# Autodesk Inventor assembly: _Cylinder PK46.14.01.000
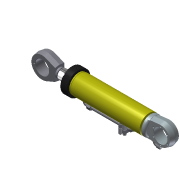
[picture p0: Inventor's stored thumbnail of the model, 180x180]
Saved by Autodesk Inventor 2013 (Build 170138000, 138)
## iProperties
Shininess: 64.0
Length Units: 11269
Angle Units: 11279
Time Units: 11290
Mass Units: 11283
Length Display Precision: 1
Angle Display Precision: 2
Compacted: True
Created: 2004-11
Part Number: _Cylinder PK46.14.01.000
Document SubType Name: Assembly
Designer: ELarisa
Manufacturer: Standard
Standards Organization: Custom
Density: 0.0
Volumn: 0.0
Area: 0.0
PropertySet Name: Model Information
Control State: 0
Master: False
Checked Out: False
Checked Out Date: 2008-10-15
Last Check In Date: 2008-10-15
Author: ELarisa
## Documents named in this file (11)
- C:\Product Design Suite 2013 Test Drive\Model Based Documentation\Workspace\_Cylinder PK46.14.01.000.iam
- C:\Product Design Suite 2013 Test Drive\Model Based Documentation\Workspace\Assemblies\PK46.14.01.010.iam
- C:\Product Design Suite 2013 Test Drive\Model Based Documentation\Workspace\Assemblies\PK46.14.01.020.iam
- C:\Product Design Suite 2013 Test Drive\Model Based Documentation\Workspace\Parts\PK46.14.01.003.ipt
- C:\Product Design Suite 2013 Test Drive\Model Based Documentation\Workspace\Parts\PK46.14.01.004.ipt
- C:\Product Design Suite 2013 Test Drive\Model Based Documentation\Workspace\Parts\PK46.14.01.005.ipt
- C:\Product Design Suite 2013 Test Drive\Model Based Documentation\Workspace\Parts\PK46.14.01.006.ipt
- C:\Product Design Suite 2013 Test Drive\Model Based Documentation\Workspace\Parts\PK46.14.01.015.ipt
- C:\Product Design Suite 2013 Test Drive\Model Based Documentation\Workspace\Parts\PK46.14.01.016.ipt
- C:\Product Design Suite 2013 Test Drive\Model Based Documentation\Workspace\Parts\8.65G.019.ipt
- C:\Product Design Suite 2013 Test Drive\Model Based Documentation\Workspace\Parts\M8-6gx45.58.019(S13).ipt
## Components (12 placed, 10 different names)
1. PK46.14.01.020:1 [sub-assembly] — Insert:80, Mate:7, Mate:9, CylinderStroke, Mate:11, Mate:12, Flush:3
2. PK46.14.01.010:1 [sub-assembly] — Insert:1, Mate:4, Mate:7
3. PK46.14.01.003:1 — Insert:1, CylinderStroke
4. PK46.14.01.004:1 — Insert:80, Insert:81
5. PK46.14.01.005:1 — Insert:81, Insert:82
6. PK46.14.01.006:1 — Insert:82, Mate:11
7. PK46.14.01.015:1 — Flush:1, Mate:5
8. PK46.14.01.016:1 — Flush:2, Mate:5, Insert:88, Insert:89
9. 8.65G.019:25 — Insert:88, Insert:90
10. 8.65G.019:26 — Insert:89, Insert:91
11. M8-6gx45.58.019(S13):1 — Insert:90
12. M8-6gx45.58.019(S13):2 — Insert:91
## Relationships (18: Insert 8, Mate 7, Flush 3)
- Insert:1: PK46.14.01.010:1 ↔ PK46.14.01.003:1
- Insert:80: PK46.14.01.020:1 ↔ PK46.14.01.004:1
- Insert:81: PK46.14.01.004:1 ↔ PK46.14.01.005:1
- Insert:82: PK46.14.01.005:1 ↔ PK46.14.01.006:1
- Flush:1: PK46.14.01.015:1
- Flush:2: PK46.14.01.016:1
- Mate:4: PK46.14.01.010:1
- Mate:5: PK46.14.01.015:1 ↔ PK46.14.01.016:1
- Insert:88: PK46.14.01.016:1 ↔ 8.65G.019:25
- Insert:89: PK46.14.01.016:1 ↔ 8.65G.019:26
- Insert:90: 8.65G.019:25 ↔ M8-6gx45.58.019(S13):1
- Insert:91: 8.65G.019:26 ↔ M8-6gx45.58.019(S13):2
- Mate:7: PK46.14.01.020:1 ↔ PK46.14.01.010:1
- Mate:9: PK46.14.01.020:1
- CylinderStroke [Mate]: PK46.14.01.020:1 ↔ PK46.14.01.003:1
- Mate:11: PK46.14.01.020:1 ↔ PK46.14.01.006:1
- Mate:12: PK46.14.01.020:1
- Flush:3: PK46.14.01.020:1
